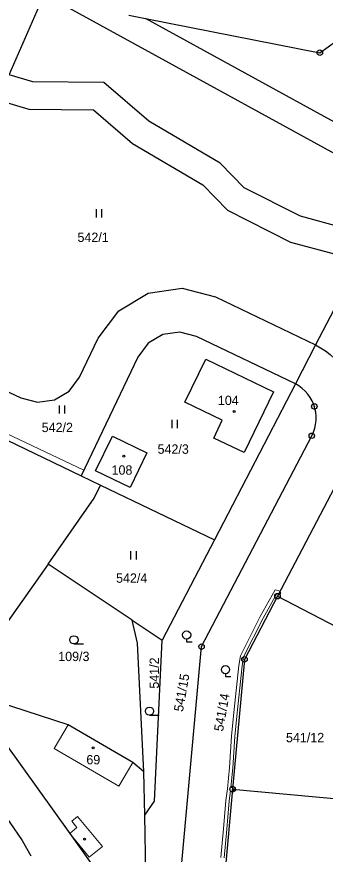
# Model space of a CAD drawing. Extents: x -759947 to -757003, y -1019641 to -1017100.
# Drawn here: x -757970.6 to -757914.5, y -1019204.8 to -1019052.2 of the extents above; entities that cross this region are included whole.
import ezdxf
from ezdxf.enums import TextEntityAlignment as Align

# ---------------------------------------------------------------- set-up
doc = ezdxf.new("R2010")
doc.units = 0
doc.header["$LTSCALE"] = 0.68
for name, color, linetype, lineweight in [('1', 7, 'Continuous', 25), ('13', 7, 'Continuous', 13), ('3', 7, 'Continuous', 25), ('4', 7, 'Continuous', 13), ('5', 7, 'Continuous', 25), ('8', 7, 'Continuous', 25)]:
    doc.layers.add(name, color=color, linetype=linetype, lineweight=lineweight)
doc.layers.add('2', color=7, linetype='Continuous')

msp = doc.modelspace()

# ---------------------------------------------------------------- linework, layer by layer
at = {"layer": '1'}
for p, q in [((-757915.46, -1019058.79), (-757900.92, -1019048.35)), ((-757971.99, -1019062.81), (-757966.03, -1019049.17)), ((-757963.05, -1019049.56), (-757891.09, -1019089.05)), ((-757950.23, -1019051.96), (-757947.21, -1019052.53)), ((-757947.21, -1019052.53), (-757915.46, -1019058.79)), ((-757890.77, -1019083.52), (-757947.21, -1019052.53)), ((-757967.68, -1019064.09), (-757971.99, -1019062.81)), ((-757954.77, -1019064.2), (-757967.68, -1019064.09)), ((-757946.61, -1019071.28), (-757954.77, -1019064.2)), ((-757973.55, -1019067.56), (-757968.43, -1019069.08)), ((-757968.43, -1019069.08), (-757956.66, -1019069.18)), ((-757956.66, -1019069.18), (-757949.54, -1019075.36)), ((-757933.62, -1019078.92), (-757946.61, -1019071.28)), ((-757949.54, -1019075.36), (-757936.73, -1019082.89)), ((-757929.24, -1019083.4), (-757933.62, -1019078.92)), ((-757936.73, -1019082.89), (-757932.24, -1019087.49)), ((-757918.97, -1019088.6), (-757929.24, -1019083.4)), ((-757932.24, -1019087.49), (-757920.78, -1019093.29)), ((-757911.01, -1019090.78), (-757918.97, -1019088.6)), ((-757920.78, -1019093.29), (-757912.86, -1019095.46)), ((-757908.76, -1019097.64), (-757916.23, -1019112.03)), ((-757946.69, -1019102.59), (-757940.49, -1019101.71)), ((-757940.49, -1019101.71), (-757934.43, -1019103.27)), ((-757952.07, -1019105.79), (-757946.69, -1019102.59)), ((-757934.43, -1019103.27), (-757916.23, -1019112.03)), ((-757955.82, -1019110.81), (-757952.07, -1019105.79)), ((-757940.93, -1019109.69), (-757944.03, -1019110.14)), ((-757937.9, -1019110.47), (-757940.93, -1019109.69)), ((-757959.21, -1019117.93), (-757955.82, -1019110.81)), ((-757944.03, -1019110.14), (-757946.72, -1019111.73)), ((-757919.91, -1019119.14), (-757937.9, -1019110.47)), ((-757990.27, -1019111.89), (-757969.9, -1019121.7)), ((-757946.72, -1019111.73), (-757948.59, -1019114.24)), ((-757916.23, -1019112.03), (-757919.91, -1019119.14)), ((-757948.59, -1019114.24), (-757958.89, -1019135.88)), ((-757940.02, -1019122.47), (-757936.2, -1019114.61)), ((-757936.2, -1019114.61), (-757923.9, -1019120.55)), ((-757961.08, -1019120.44), (-757959.21, -1019117.93)), ((-757919.91, -1019119.14), (-757934.65, -1019147.54)), ((-757990.9, -1019120.47), (-757958.89, -1019135.88)), ((-757963.77, -1019122.03), (-757961.08, -1019120.44)), ((-757923.9, -1019120.55), (-757929.25, -1019131.63)), ((-757969.9, -1019121.7), (-757966.87, -1019122.48)), ((-757966.87, -1019122.48), (-757963.77, -1019122.03)), ((-757933.24, -1019125.76), (-757940.02, -1019122.47)), ((-757934.76, -1019129), (-757933.24, -1019125.76)), ((-757956.28, -1019135), (-757953.21, -1019128.68)), ((-757953.21, -1019128.68), (-757946.95, -1019131.67)), ((-757936.99, -1019167.01), (-757916.92, -1019128.58)), ((-757929.25, -1019131.63), (-757934.76, -1019129)), ((-757946.95, -1019131.67), (-757949.95, -1019138)), ((-757909.82, -1019132.26), (-757923.16, -1019157.81)), ((-757958.89, -1019135.88), (-757955.35, -1019137.58)), ((-757949.95, -1019138), (-757956.28, -1019135)), ((-757956.53, -1019139.98), (-757955.35, -1019137.58)), ((-757955.35, -1019137.58), (-757934.65, -1019147.54)), ((-757964.93, -1019151.99), (-757956.53, -1019139.98)), ((-757934.65, -1019147.54), (-757944.14, -1019165.84)), ((-757964.93, -1019151.99), (-757973.01, -1019163.54)), ((-757949.61, -1019162.19), (-757964.93, -1019151.99)), ((-757923.16, -1019157.81), (-757929.17, -1019169.32)), ((-757923.16, -1019157.81), (-757898.33, -1019170.78)), ((-757948.65, -1019166.38), (-757949.61, -1019162.19)), ((-757949.61, -1019162.19), (-757944.14, -1019165.84)), ((-757947.47, -1019189.79), (-757948.65, -1019166.38)), ((-757945.54, -1019195.16), (-757944.14, -1019165.84)), ((-757941.23, -1019213.24), (-757936.99, -1019167.01)), ((-757929.17, -1019169.32), (-757931.34, -1019192.98)), ((-757961.26, -1019181.24), (-757978.74, -1019175.6)), ((-757949.49, -1019188.14), (-757961.26, -1019181.24)), ((-757972.59, -1019184.77), (-757960.98, -1019201.07)), ((-757947.47, -1019189.79), (-757949.49, -1019188.14)), ((-757947.31, -1019197.72), (-757947.47, -1019189.79)), ((-757975.86, -1019193.31), (-757969.64, -1019202.3)), ((-757931.34, -1019192.98), (-757933.24, -1019213.74)), ((-757931.34, -1019192.98), (-757904.03, -1019195.48)), ((-757947.31, -1019197.72), (-757945.54, -1019195.16)), ((-757947.07, -1019210.08), (-757947.31, -1019197.72)), ((-757960.98, -1019201.07), (-757955.05, -1019209.35)), ((-757969.64, -1019202.3), (-757968.05, -1019205.15))]:
    msp.add_line(p, q, dxfattribs=at)
for points in [[(-757916.23, -1019112.03), (-757915.31, -1019112.551), (-757914.429, -1019113.136), (-757913.591, -1019113.78), (-757912.8, -1019114.482), (-757912.06, -1019115.237), (-757911.375, -1019116.043), (-757910.748, -1019116.894), (-757910.181, -1019117.787), (-757909.679, -1019118.717), (-757909.243, -1019119.68), (-757908.875, -1019120.672), (-757908.578, -1019121.686), (-757908.352, -1019122.719), (-757908.199, -1019123.766), (-757908.12, -1019124.82)], [(-757916.92, -1019128.58), (-757916.617, -1019127.913), (-757916.385, -1019127.217), (-757916.228, -1019126.502), (-757916.145, -1019125.773), (-757916.14, -1019125.04), (-757916.211, -1019124.311), (-757916.358, -1019123.593), (-757916.58, -1019122.894), (-757916.873, -1019122.223), (-757917.234, -1019121.585), (-757917.661, -1019120.989), (-757918.147, -1019120.441), (-757918.688, -1019119.946), (-757919.278, -1019119.511), (-757919.91, -1019119.14)]]:
    msp.add_lwpolyline(points, dxfattribs=at)
at = {"layer": '13'}
msp.add_lwpolyline([(-757988.57, -1019121.59), (-757984.31, -1019123.65), (-757982.76, -1019124.39), (-757958.89, -1019135.88), (-757958.41, -1019134.86), (-757984.34, -1019122.61)], close=True, dxfattribs=at)
for points in [[(-757931.32, -1019189.08), (-757930.91, -1019183.38), (-757930.51, -1019179.04), (-757929.59, -1019170.51), (-757929.34, -1019168.88), (-757925.77, -1019161.82), (-757923.29, -1019157.34), (-757922.96, -1019157.42), (-757922.75, -1019157.48), (-757922.56, -1019157.18), (-757922.76, -1019157.05), (-757922.67, -1019156.87), (-757923.59, -1019156.66), (-757926.31, -1019161.54), (-757929.92, -1019168.7), (-757930.19, -1019170.43), (-757931.11, -1019178.98), (-757931.51, -1019183.34), (-757931.92, -1019189.04), (-757932.28, -1019192.92), (-757932.54, -1019195.02), (-757932.97, -1019200.22)], [(-757932.88, -1019205.46), (-757932.37, -1019200.28), (-757931.94, -1019195.08), (-757931.72, -1019193.28), (-757931.37, -1019193.32), (-757931.12, -1019193.27), (-757931.08, -1019193), (-757931.07, -1019192.93), (-757931.33, -1019192.89), (-757931.32, -1019192.73), (-757931.65, -1019192.69), (-757931.32, -1019189.08)], [(-757932.97, -1019200.22), (-757933.48, -1019205.4)]]:
    msp.add_lwpolyline(points, dxfattribs=at)
at = {"layer": '3'}
for p, q in [((-757956.111, -1019088.8), (-757956.111, -1019087.3)), ((-757955.11, -1019088.8), (-757955.11, -1019087.3)), ((-757962.871, -1019124.54), (-757962.871, -1019123.04)), ((-757961.87, -1019124.54), (-757961.87, -1019123.04)), ((-757942.351, -1019127.2), (-757942.351, -1019125.7)), ((-757941.35, -1019127.2), (-757941.35, -1019125.7)), ((-757949.841, -1019151.11), (-757949.841, -1019149.61)), ((-757948.84, -1019151.11), (-757948.84, -1019149.61)), ((-757960.223, -1019166.51), (-757958.473, -1019166.51)), ((-757946.463, -1019179.52), (-757944.713, -1019179.52))]:
    msp.add_line(p, q, dxfattribs=at)
for points in [[(-757939.71, -1019165.622), (-757939.71, -1019166.12), (-757938.709, -1019166.12)], [(-757932.63, -1019171.952), (-757932.63, -1019172.45), (-757931.629, -1019172.45)]]:
    msp.add_lwpolyline(points, dxfattribs=at)
for centre in [(-757960.2229, -1019165.7598), (-757939.7093, -1019164.8709), (-757932.6293, -1019171.2009), (-757946.4629, -1019178.7698)]:
    msp.add_circle(centre, 0.75, dxfattribs=at)
at = {"layer": '4'}
for p, q in [((-757961.26, -1019181.24), (-757963.79, -1019185.55)), ((-757952.02, -1019192.45), (-757963.79, -1019185.55)), ((-757949.49, -1019188.14), (-757952.02, -1019192.45)), ((-757960.62, -1019198.82), (-757959.55, -1019197.93)), ((-757959.55, -1019197.93), (-757955.02, -1019203.42)), ((-757960.98, -1019201.07), (-757959.67, -1019199.99)), ((-757959.67, -1019199.99), (-757960.62, -1019198.82)), ((-757957.42, -1019205.39), (-757960.98, -1019201.07)), ((-757955.02, -1019203.42), (-757957.42, -1019205.39))]:
    msp.add_line(p, q, dxfattribs=at)
at = {"layer": '5'}
for centre in [(-757931.0368, -1019124.1792), (-757951.1268, -1019132.3192), (-757956.6968, -1019185.4492), (-757958.2665, -1019202.0779)]:
    msp.add_circle(centre, 0.175, dxfattribs=at)
at = {"layer": '8'}
for centre, radius in [((-757915.46, -1019058.7899), 0.5), ((-757915.46, -1019058.7899), 0.0303), ((-757916.46, -1019123.2399), 0.5), ((-757916.46, -1019123.2399), 0.0303), ((-757916.92, -1019128.5799), 0.5), ((-757916.92, -1019128.5799), 0.0303), ((-757923.16, -1019157.8099), 0.5), ((-757923.16, -1019157.8099), 0.0303), ((-757936.99, -1019167.0099), 0.5), ((-757936.99, -1019167.0099), 0.0303), ((-757929.17, -1019169.3199), 0.5), ((-757929.17, -1019169.3199), 0.0303), ((-757931.34, -1019192.9799), 0.5), ((-757931.34, -1019192.9799), 0.0303)]:
    msp.add_circle(centre, radius, dxfattribs=at)

# ---------------------------------------------------------------- texts
at = {"layer": '2'}
for s, p in [('542/1', (-757956.72, -1019093.265)), ('104', (-757932.119, -1019122.985)), ('542/2', (-757963.24, -1019127.915)), ('542/3', (-757942.15, -1019131.865)), ('108', (-757951.469, -1019135.675)), ('542/4', (-757949.7, -1019155.365)), ('109/3', (-757960.23, -1019169.635)), ('69', (-757956.689, -1019188.455))]:
    msp.add_text(s, height=1.7, dxfattribs=at).set_placement(p, align=Align.CENTER)
for s, rotation, p in [('541/2', 90, (-757944.745, -1019174.66)), ('541/15', 80, (-757940.381, -1019178.953)), ('541/14', 80, (-757933.081, -1019182.543))]:
    msp.add_text(s, height=1.7, rotation=rotation, dxfattribs=at).set_placement(p)
msp.add_text('541/12', height=1.7, dxfattribs=at).set_placement((-757921.62, -1019184.425))

doc.saveas('drawing.dxf')
